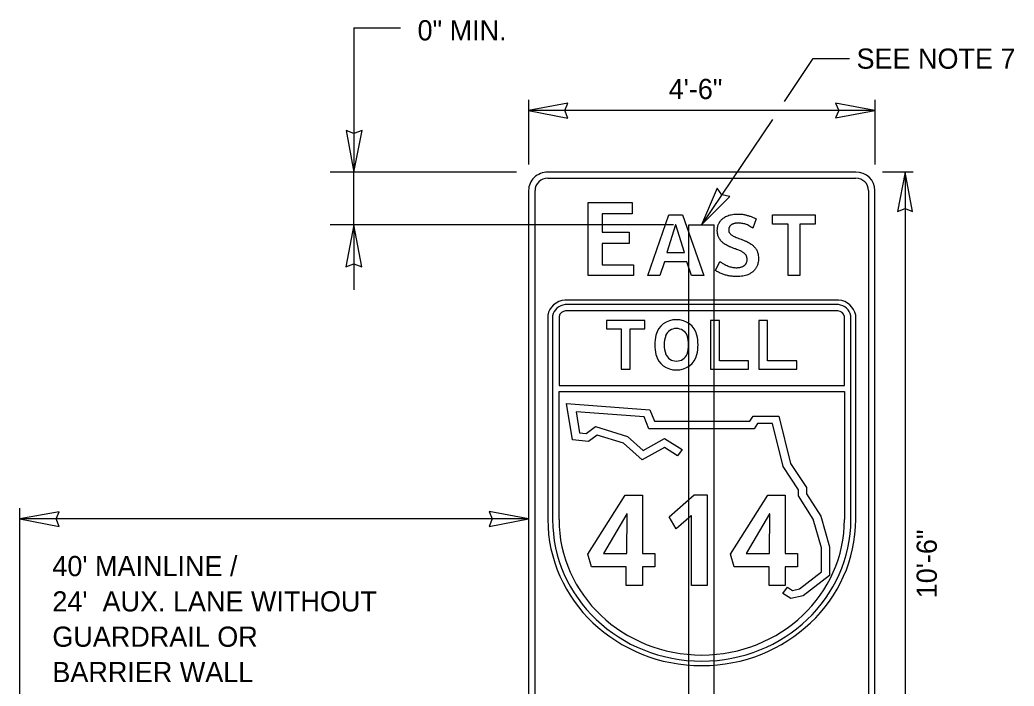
# Model space of a CAD drawing. Extents: x 34 to 667, y 20 to 415.
# Drawn here: x 100.2 to 238.2, y 316.8 to 409.3 of the extents above; entities that cross this region are included whole.
import ezdxf

# ---------------------------------------------------------------- set-up
doc = ezdxf.new("R2010")
doc.units = 0
for name, color, linetype in [('Default', 7, 'Continuous'), ('LeaderLine_dp', 7, 'Continuous'), ('SignPanel', 7, 'Continuous')]:
    doc.layers.add(name, color=color, linetype=linetype)

msp = doc.modelspace()

# ---------------------------------------------------------------- linework, layer by layer
at = {"layer": 'Default'}
for p, q in [((196.99, 385.91), (194.8, 380.82)), ((197.61, 385), (196.99, 385.91)), ((198.71, 384.75), (197.61, 385)), ((194.8, 380.82), (198.71, 384.75)), ((187.36, 373.8), (190.27, 382.25)), ((190.27, 382.25), (192.15, 382.25)), ((192.15, 382.25), (195.12, 373.8)), ((204.65, 380.93), (204.65, 382.23)), ((204.65, 382.23), (210.59, 382.23)), ((210.59, 382.23), (210.59, 380.93)), ((193.03, 281.63), (193.03, 380.82)), ((193.03, 380.82), (196.56, 380.82)), ((196.56, 281.63), (196.56, 380.82)), ((206.82, 380.93), (204.65, 380.93)), ((206.82, 373.8), (206.82, 380.93)), ((208.42, 380.93), (208.42, 373.8)), ((210.59, 380.93), (208.42, 380.93)), ((189.68, 375.72), (189.03, 373.8)), ((192.75, 375.72), (189.68, 375.72)), ((193.4, 373.8), (192.75, 375.72)), ((189.03, 373.8), (187.36, 373.8)), ((195.12, 373.8), (193.4, 373.8)), ((208.42, 373.8), (206.82, 373.8)), ((194.83, 369.77), (175.88, 369.77)), ((213.79, 369.77), (194.83, 369.77)), ((186.93, 367.57), (181.62, 367.57)), ((181.62, 367.57), (181.62, 366.39)), ((186.93, 367.57), (181.62, 367.57)), ((181.62, 367.57), (181.62, 366.39)), ((186.93, 366.39), (186.93, 367.57)), ((186.93, 366.39), (186.93, 367.57)), ((197.27, 367.57), (196.03, 367.57)), ((196.03, 367.57), (196.03, 360.81)), ((197.27, 367.57), (196.03, 367.57)), ((196.03, 367.57), (196.03, 360.81)), ((197.27, 361.99), (197.27, 367.57)), ((197.27, 361.99), (197.27, 367.57)), ((203.97, 367.57), (202.73, 367.57)), ((202.73, 367.57), (202.73, 360.81)), ((203.97, 367.57), (202.73, 367.57)), ((202.73, 367.57), (202.73, 360.81)), ((203.97, 361.99), (203.97, 367.57)), ((203.97, 361.99), (203.97, 367.57)), ((181.62, 366.39), (183.65, 366.39)), ((181.62, 366.39), (183.65, 366.39)), ((183.65, 366.39), (183.65, 360.81)), ((183.65, 366.39), (183.65, 360.81)), ((184.9, 360.81), (184.9, 366.39)), ((184.9, 366.39), (186.93, 366.39)), ((184.9, 360.81), (184.9, 366.39)), ((184.9, 366.39), (186.93, 366.39)), ((201.33, 361.99), (197.27, 361.99)), ((201.33, 361.99), (197.27, 361.99)), ((201.33, 360.81), (201.33, 361.99)), ((201.33, 360.81), (201.33, 361.99)), ((208.03, 361.99), (203.97, 361.99)), ((208.03, 361.99), (203.97, 361.99)), ((208.03, 360.81), (208.03, 361.99)), ((208.03, 360.81), (208.03, 361.99)), ((183.65, 360.81), (184.9, 360.81)), ((183.65, 360.81), (184.9, 360.81)), ((196.03, 360.81), (201.33, 360.81)), ((196.03, 360.81), (201.33, 360.81)), ((202.73, 360.81), (208.03, 360.81)), ((202.73, 360.81), (208.03, 360.81)), ((176.89, 351.02), (176.07, 356.03)), ((176.07, 356.03), (187.61, 355.19)), ((186.82, 354.19), (177.38, 354.88)), ((177.38, 354.88), (177.86, 351.97)), ((187.61, 355.19), (188.25, 353.61)), ((187.49, 352.56), (186.82, 354.19)), ((188.25, 353.61), (201.48, 353.61)), ((201.48, 353.61), (201.98, 354.31)), ((201.98, 354.31), (205.54, 354.31)), ((202.57, 353.26), (202.08, 352.56)), ((204.66, 353.26), (202.57, 353.26)), ((206.11, 347.32), (204.66, 353.26)), ((205.54, 354.31), (207.16, 347.73)), ((177.86, 351.97), (178.77, 351.87)), ((178.77, 351.87), (180.09, 352.85)), ((180.09, 352.85), (184.54, 351.47)), ((202.08, 352.56), (187.49, 352.56)), ((179.1, 350.76), (176.89, 351.02)), ((180.31, 351.67), (179.1, 350.76)), ((183.96, 350.54), (180.31, 351.67)), ((186.57, 348.24), (183.96, 350.54)), ((184.54, 351.47), (186.72, 349.55)), ((186.72, 349.55), (189.68, 351.2)), ((189.68, 351.2), (192.09, 349.65)), ((189.64, 349.95), (186.57, 348.24)), ((191.47, 348.78), (189.64, 349.95)), ((192.09, 349.65), (191.47, 348.78)), ((207.16, 347.73), (209.35, 344.38)), ((208.24, 344.08), (206.11, 347.32)), ((208.24, 343.24), (208.24, 344.08)), ((209.35, 344.38), (209.35, 343.53)), ((210.3, 340.01), (208.24, 343.24)), ((209.35, 343.53), (211.34, 340.43)), ((211.44, 336.04), (210.3, 340.01)), ((211.34, 340.43), (212.56, 336.18)), ((211.44, 332.71), (211.44, 336.04)), ((212.56, 336.18), (212.56, 332.21)), ((208.41, 330.35), (211.44, 332.71)), ((212.56, 332.21), (208.91, 329.37)), ((206.09, 329.7), (206.72, 330.57)), ((206.72, 330.57), (207.41, 330.12)), ((207.41, 330.12), (208.41, 330.35)), ((207.18, 328.98), (206.09, 329.7)), ((208.91, 329.37), (207.18, 328.98))]:
    msp.add_line(p, q, dxfattribs=at)
for points in [[(179.08, 373.8), (179.08, 383.92), (185.17, 383.92), (185.17, 382.37), (180.99, 382.37), (180.99, 379.82), (184.77, 379.82), (184.77, 378.26), (180.99, 378.26), (180.99, 375.31), (185.34, 375.31), (185.34, 373.8), (179.08, 373.8)], [(191.23, 380.82), (191.19, 380.82), (190, 376.99), (192.42, 376.99), (191.23, 380.82)], [(202.37, 381.66), (201.9, 380.39)], [(196.72, 374.5), (197.32, 375.76)], [(213.82, 370.41), (175.84, 370.41)], [(213.73, 368.93), (175.93, 368.93)], [(173.47, 368.29), (173.47, 339.97)], [(174.13, 368.24), (174.13, 339.97)], [(175.03, 368.15), (175.03, 358.57), (214.64, 358.57)], [(214.64, 358.57), (214.64, 368.15)], [(215.53, 339.97), (215.53, 368.24)], [(216.2, 339.97), (216.2, 368.29)], [(175.03, 339.97), (175.03, 357.73), (214.64, 357.73), (214.64, 339.97)], [(186.59, 333.37), (186.59, 330.81), (184.35, 330.81), (184.35, 333.37), (179.52, 333.37), (179.01, 335.13), (184.18, 343.34), (186.59, 343.34), (186.59, 335.26), (188.3, 335.26), (188.3, 333.37), (186.59, 333.37)], [(193.39, 330.81), (193.4, 340.49), (193.35, 340.49), (191.3, 338.68), (190.31, 340.32), (193.78, 343.39), (195.57, 343.39), (195.57, 330.81), (193.39, 330.81)], [(206.41, 333.37), (206.41, 330.81), (204.17, 330.81), (204.17, 333.37), (199.33, 333.37), (198.83, 335.13), (203.99, 343.34), (206.41, 343.34), (206.41, 335.26), (208.11, 335.26), (208.11, 333.37), (206.41, 333.37)], [(184.41, 340.73), (181.2, 335.26), (184.42, 335.26), (184.46, 340.73), (184.41, 340.73)], [(204.22, 340.73), (201.01, 335.26), (204.23, 335.26), (204.27, 340.73), (204.22, 340.73)]]:
    msp.add_lwpolyline(points, dxfattribs=at)
for points in [[(181.62, 366.39), (183.65, 366.39), (183.65, 360.81), (184.9, 360.81), (184.9, 366.39), (186.93, 366.39), (186.93, 367.57), (181.62, 367.57)], [(201.33, 360.81), (201.33, 361.99), (197.27, 361.99), (197.27, 367.57), (196.03, 367.57), (196.03, 360.81)], [(208.03, 360.81), (208.03, 361.99), (203.97, 361.99), (203.97, 367.57), (202.73, 367.57), (202.73, 360.81)]]:
    msp.add_lwpolyline(points, close=True, dxfattribs=at)
for centre, major_axis, start_param, end_param in [((176.1, 367.88), (2.67, 0), 1.668878, 2.979017), ((213.56, 367.88), (2.67, 0), 0.162576, 1.472714), ((176.1, 367.88), (2, 0), 1.684067, 2.953797), ((176.1, 367.88), (1.11, 0), 1.72283, 2.88934), ((213.56, 367.88), (1.11, 0), 0.252252, 1.418763), ((213.56, 367.88), (2, 0), 0.187795, 1.457526), ((191.27, 364.95), (2.87, 0), 1.556517, 2.923458), ((191.27, 364.95), (2.87, 0), 1.556517, 2.923458), ((191.27, 364.95), (2.87, 0), 1.556517, 2.923458), ((191.35, 364.95), (2.87, 0), 0.218134, 1.585075), ((191.35, 364.95), (2.87, 0), 0.218134, 1.585075), ((191.35, 364.95), (2.87, 0), 0.218134, 1.585075), ((191.32, 364.92), (1.62, 0), 1.578746, 2.762765), ((191.32, 364.92), (1.62, 0), 1.578746, 2.762765), ((191.32, 364.92), (1.62, 0), 1.578746, 2.762765), ((191.3, 364.92), (1.62, 0), 0.378827, 1.562847), ((191.3, 364.92), (1.62, 0), 0.378827, 1.562847), ((191.3, 364.92), (1.62, 0), 0.378827, 1.562847), ((195.36, 364.16), (7.04, 0), 2.93356, 3.136663), ((195.36, 364.16), (7.04, 0), 2.93356, 3.136663), ((195.36, 364.16), (7.04, 0), 2.93356, 3.136663), ((193.96, 364.2), (4.35, 0), 2.825907, 3.14372), ((193.96, 364.2), (4.35, 0), 2.825907, 3.14372), ((193.96, 364.2), (4.35, 0), 2.825907, 3.14372), ((188.66, 364.2), (4.35, 0), 6.281058, 6.598871), ((188.66, 364.2), (4.35, 0), 6.281058, 6.598871), ((188.66, 364.2), (4.35, 0), 6.281058, 6.598871), ((187.27, 364.16), (7.04, 0), 0.00493, 0.208032), ((187.27, 364.16), (7.04, 0), 0.00493, 0.208032), ((187.27, 364.16), (7.04, 0), 0.00493, 0.208032), ((195.36, 364.23), (7.04, 0), 3.146522, 3.349625), ((195.36, 364.23), (7.04, 0), 3.146522, 3.349625), ((195.36, 364.23), (7.04, 0), 3.146522, 3.349625), ((193.96, 364.18), (4.35, 0), 3.139465, 3.457279), ((193.96, 364.18), (4.35, 0), 3.139465, 3.457279), ((193.96, 364.18), (4.35, 0), 3.139465, 3.457279), ((191.32, 363.47), (1.62, 0), 3.52042, 4.704439), ((191.32, 363.47), (1.62, 0), 3.52042, 4.704439), ((191.32, 363.47), (1.62, 0), 3.52042, 4.704439), ((191.3, 363.47), (1.62, 0), 4.720339, 5.904358), ((191.3, 363.47), (1.62, 0), 4.720559, 5.904358), ((191.3, 363.47), (1.62, 0), 4.720559, 5.904358), ((188.66, 364.18), (4.35, 0), 5.967499, 6.285313), ((188.66, 364.18), (4.35, 0), 5.967499, 6.285313), ((188.66, 364.18), (4.35, 0), 5.967499, 6.285313), ((187.27, 364.23), (7.04, 0), 6.075153, 6.278256), ((187.27, 364.23), (7.04, 0), 6.075153, 6.278256), ((187.27, 364.23), (7.04, 0), 6.075153, 6.278256), ((191.27, 363.43), (2.87, 0), 3.359727, 4.726668), ((191.27, 363.43), (2.87, 0), 3.359727, 4.726668), ((191.27, 363.43), (2.87, 0), 3.359727, 4.726668), ((191.35, 363.43), (2.87, 0), 4.69811, 6.065051), ((191.35, 363.43), (2.87, 0), 4.698234, 6.065051), ((191.35, 363.43), (2.87, 0), 4.698234, 6.065051), ((194.83, 339.97), (21.36, 0), 3.141593, 6.283185), ((194.83, 339.97), (20.7, 0), 3.141593, 4.712389), ((194.83, 339.97), (19.81, 0), 3.141593, 4.712389), ((194.83, 339.97), (20.7, 0), 4.712406, 6.283185), ((194.83, 339.97), (19.81, 0), 4.712407, 6.283185)]:
    msp.add_ellipse(centre, major_axis=major_axis, ratio=0.949725, start_param=start_param, end_param=end_param, dxfattribs=at)
for points in [[(196.99, 380.06), (196.99, 380.11), (196.99, 380.25), (197.02, 380.48), (197.08, 380.74), (197.15, 380.95), (197.23, 381.09), (197.31, 381.23), (197.42, 381.4), (197.58, 381.58), (197.73, 381.71), (197.89, 381.83), (198.13, 381.98), (198.44, 382.12), (198.76, 382.21), (199.1, 382.29), (199.45, 382.34), (199.72, 382.34), (199.81, 382.34)], [(199.81, 382.34), (199.93, 382.34), (200.27, 382.33), (200.72, 382.27), (201.15, 382.16), (201.57, 382.03), (201.98, 381.86), (202.27, 381.71), (202.37, 381.66)], [(199.93, 381.08), (199.84, 381.08), (199.7, 381.08), (199.53, 381.06), (199.41, 381.04), (199.25, 381), (199.12, 380.95), (199.02, 380.9), (198.98, 380.88), (198.92, 380.84), (198.85, 380.78), (198.77, 380.71), (198.72, 380.64), (198.68, 380.57), (198.64, 380.51), (198.61, 380.42), (198.58, 380.31), (198.57, 380.2), (198.57, 380.14), (198.57, 380.12)], [(201.9, 380.39), (201.83, 380.44), (201.61, 380.59), (201.29, 380.76), (201.02, 380.88), (200.82, 380.96), (200.56, 381.03), (200.25, 381.07), (200.02, 381.08), (199.93, 381.08)], [(199.52, 377.49), (199.37, 377.55), (199.07, 377.66), (198.7, 377.81), (198.34, 377.97), (198.07, 378.13), (197.85, 378.29), (197.7, 378.42), (197.53, 378.58), (197.36, 378.79), (197.24, 378.99), (197.15, 379.17), (197.08, 379.37), (197.02, 379.63), (196.99, 379.86), (196.99, 380.01), (196.99, 380.06)], [(198.57, 380.12), (198.57, 380.1), (198.57, 380.04), (198.58, 379.94), (198.62, 379.83), (198.66, 379.74), (198.71, 379.68), (198.8, 379.57), (198.93, 379.45), (199.09, 379.34), (199.31, 379.22), (199.6, 379.09), (199.96, 378.96), (200.18, 378.88), (200.29, 378.83)], [(200.29, 378.83), (200.43, 378.78), (200.72, 378.67), (201.07, 378.52), (201.42, 378.35), (201.68, 378.18), (201.89, 378.02), (202.03, 377.89), (202.19, 377.72), (202.35, 377.5), (202.47, 377.3), (202.55, 377.12), (202.62, 376.91), (202.69, 376.6), (202.7, 376.37), (202.7, 376.22)], [(201.12, 376.07), (201.12, 376.09), (201.12, 376.16), (201.11, 376.27), (201.08, 376.4), (201.04, 376.51), (201, 376.58), (200.95, 376.65), (200.87, 376.76), (200.77, 376.87), (200.64, 376.97), (200.49, 377.07), (200.32, 377.17), (200.08, 377.28), (199.83, 377.38), (199.62, 377.45), (199.52, 377.49)], [(197.32, 375.76), (197.41, 375.71), (197.67, 375.53), (198.03, 375.32), (198.36, 375.17), (198.6, 375.07), (198.85, 374.99), (199.16, 374.92), (199.43, 374.9), (199.59, 374.89), (199.64, 374.89)], [(199.64, 374.89), (199.69, 374.89), (199.83, 374.9), (200.01, 374.92), (200.19, 374.95), (200.36, 374.99), (200.52, 375.06), (200.65, 375.13), (200.74, 375.19), (200.81, 375.26), (200.9, 375.35), (200.96, 375.43), (201, 375.5), (201.04, 375.58), (201.08, 375.69), (201.12, 375.86), (201.12, 375.99), (201.12, 376.07)], [(202.7, 376.22), (202.7, 376.11), (202.69, 375.85), (202.63, 375.51), (202.55, 375.23), (202.48, 375.06), (202.4, 374.91), (202.29, 374.73), (202.13, 374.53), (201.98, 374.38), (201.85, 374.27), (201.71, 374.17), (201.53, 374.06), (201.25, 373.92), (200.94, 373.82), (200.52, 373.73), (200.13, 373.68), (199.82, 373.67), (199.72, 373.67)], [(199.72, 373.67), (199.58, 373.68), (199.17, 373.68), (198.63, 373.75), (198.13, 373.87), (197.64, 374.03), (197.17, 374.24), (196.83, 374.43), (196.72, 374.5)]]:
    msp.add_open_spline(points, degree=3, dxfattribs=at)
at = {"layer": 'LeaderLine_dp'}
for p, q in [((146.56, 408.19), (146.56, 388.15)), ((146.56, 408.19), (153.02, 408.19)), ((206.3, 397.94), (210.31, 403.9)), ((210.31, 403.9), (215.31, 403.9)), ((170.8, 398.19), (170.8, 389.2)), ((176.25, 397.71), (170.8, 396.69)), ((175.83, 396.69), (176.25, 397.71)), ((218.87, 396.69), (213.41, 397.74)), ((213.41, 397.74), (213.83, 396.69)), ((218.87, 398.19), (218.87, 389.2)), ((170.8, 396.69), (176.25, 395.64)), ((218.87, 396.69), (170.8, 396.69)), ((176.25, 395.64), (175.83, 396.69)), ((213.83, 396.69), (213.41, 395.68)), ((213.41, 395.68), (218.87, 396.69)), ((146.56, 393.51), (145.48, 393.95)), ((145.48, 393.95), (146.56, 388.15)), ((146.56, 388.15), (147.69, 393.95)), ((147.69, 393.95), (146.56, 393.51)), ((169.11, 388.15), (143.27, 388.15)), ((146.56, 380.82), (146.56, 388.15)), ((224.17, 388.15), (219.89, 388.15)), ((223.05, 388.15), (222, 382.7)), ((223.05, 388.15), (223.05, 281.63)), ((224.07, 382.7), (223.05, 388.15)), ((222, 382.7), (223.05, 383.11)), ((223.05, 383.11), (224.07, 382.7)), ((190.93, 380.82), (143.27, 380.82)), ((146.56, 380.82), (145.44, 375.01)), ((147.65, 375.01), (146.56, 380.82)), ((146.56, 380.82), (146.56, 371.82)), ((145.44, 375.01), (146.56, 375.45)), ((146.56, 375.45), (147.65, 375.01)), ((100.2, 237.54), (100.2, 341.53)), ((105.65, 341.04), (100.2, 340.03)), ((105.24, 340.03), (105.65, 341.04)), ((170.8, 340.03), (165.35, 341.08)), ((165.35, 341.08), (165.76, 340.03)), ((170.8, 340.03), (100.2, 340.03)), ((100.2, 340.03), (105.65, 338.98)), ((105.65, 338.98), (105.24, 340.03)), ((165.76, 340.03), (165.35, 339.01)), ((165.35, 339.01), (170.8, 340.03))]:
    msp.add_line(p, q, dxfattribs=at)
msp.add_lwpolyline([(204.63, 395.45), (194.8, 380.82)], dxfattribs=at)
at = {"layer": 'SignPanel'}
for p, q in [((216.2, 388.15), (173.47, 388.15)), ((173.47, 387.3), (216.2, 387.3)), ((170.8, 385.61), (170.8, 284.16)), ((171.69, 284.16), (171.69, 385.61)), ((217.98, 385.61), (217.98, 284.16)), ((218.87, 284.16), (218.87, 385.61))]:
    msp.add_line(p, q, dxfattribs=at)
for centre, major_axis, start_param, end_param in [((173.47, 385.61), (2.67, 0), 1.570796, 3.141593), ((216.2, 385.61), (2.67, 0), 0, 1.570796), ((173.47, 385.61), (1.78, 0), 1.570796, 3.141593), ((216.2, 385.61), (1.78, 0), 0, 1.570796)]:
    msp.add_ellipse(centre, major_axis=major_axis, ratio=0.949725, start_param=start_param, end_param=end_param, dxfattribs=at)

# ---------------------------------------------------------------- texts
at = {"layer": 'Default'}
for s, rotation, p in [('0" MIN.', 360, (155.39, 406.43)), ('SEE NOTE 7', 0, (216.31, 402.5)), ('4\'-6"', 0, (190.24, 398.29)), ('10\'-6"', 90, (227.45, 329.03)), ("40' MAINLINE /", 0, (104.71, 332.1)), ("24'  AUX. LANE WITHOUT", 0, (104.71, 327.2)), ('GUARDRAIL OR ', 0, (104.71, 322.3)), ('BARRIER WALL', 0, (104.71, 317.4))]:
    msp.add_text(s, height=2.8, rotation=rotation, dxfattribs=at).set_placement(p)

doc.saveas('drawing.dxf')
